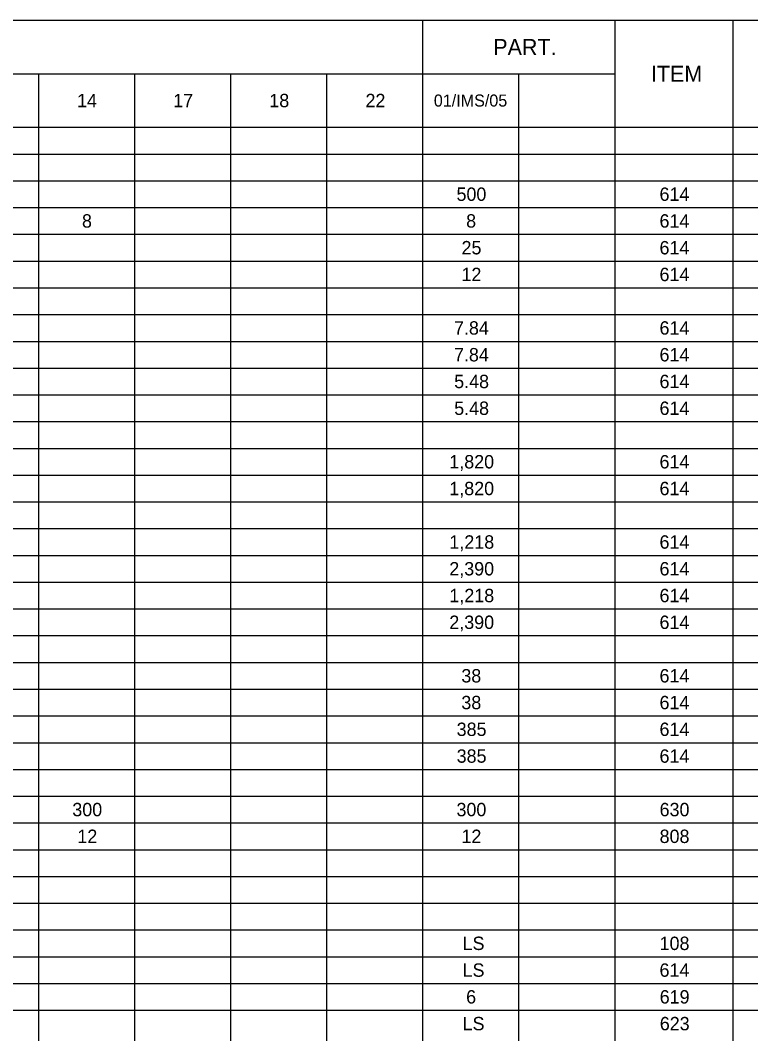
# Model space of a CAD drawing. Extents: x -32.2 to 34, y 0 to 22.
# Drawn here: x -24.34 to -16.7, y 10.89 to 21.5 of the extents above; entities that cross this region are included whole.
import ezdxf

# ---------------------------------------------------------------- set-up
doc = ezdxf.new("R2010")
doc.units = 0
doc.layers.add('SH_Text', color=7, linetype='Continuous')

msp = doc.modelspace()

# ---------------------------------------------------------------- linework, layer by layer
at = {"layer": 'SH_Text'}
for p, q in [((-32.188, 21.5), (-1.685, 21.5)), ((-20.132, 21.5), (-20.132, 0.5)), ((-18.122, 21.5), (-18.122, 0.5)), ((-16.887, 21.5), (-16.887, 0.5)), ((-32.188, 20.94), (-18.122, 20.94)), ((-24.151, 20.94), (-24.151, 0.5)), ((-23.146, 20.94), (-23.146, 0.5)), ((-22.141, 20.94), (-22.141, 0.5)), ((-21.137, 20.94), (-21.137, 0.5)), ((-19.127, 20.94), (-19.127, 0.5)), ((-32.188, 20.38), (-1.685, 20.38)), ((-32.188, 20.1), (-1.685, 20.1)), ((-32.188, 19.82), (-1.685, 19.82)), ((-32.188, 19.54), (-1.685, 19.54)), ((-32.188, 19.26), (-1.685, 19.26)), ((-32.188, 18.98), (-1.685, 18.98)), ((-32.188, 18.7), (-1.685, 18.7)), ((-32.188, 18.42), (-1.685, 18.42)), ((-32.188, 18.14), (-1.685, 18.14)), ((-32.188, 17.86), (-1.685, 17.86)), ((-32.188, 17.58), (-1.685, 17.58)), ((-32.188, 17.3), (-1.685, 17.3)), ((-32.188, 17.02), (-1.685, 17.02)), ((-32.188, 16.74), (-1.685, 16.74)), ((-32.188, 16.46), (-1.685, 16.46)), ((-32.188, 16.18), (-1.685, 16.18)), ((-32.188, 15.9), (-1.685, 15.9)), ((-32.188, 15.62), (-1.685, 15.62)), ((-32.188, 15.34), (-1.685, 15.34)), ((-32.188, 15.06), (-1.685, 15.06)), ((-32.188, 14.78), (-1.685, 14.78)), ((-32.188, 14.5), (-1.685, 14.5)), ((-32.188, 14.22), (-1.685, 14.22)), ((-32.188, 13.94), (-1.685, 13.94)), ((-32.188, 13.66), (-1.685, 13.66)), ((-32.188, 13.38), (-1.685, 13.38)), ((-32.188, 13.1), (-1.685, 13.1)), ((-32.188, 12.82), (-1.685, 12.82)), ((-32.188, 12.54), (-1.685, 12.54)), ((-32.188, 12.26), (-1.685, 12.26)), ((-32.188, 11.98), (-1.685, 11.98)), ((-32.188, 11.7), (-1.685, 11.7)), ((-32.188, 11.42), (-1.685, 11.42)), ((-32.188, 11.14), (-1.685, 11.14))]:
    msp.add_line(p, q, dxfattribs=at)

# ---------------------------------------------------------------- texts
for s, height, p in [('PART.', 0.168, (-19.392, 21.136)), ('ITEM', 0.168, (-17.743, 20.856)), ('14', 0.14, (-23.746, 20.59)), ('17', 0.14, (-22.74, 20.59)), ('18', 0.14, (-21.735, 20.59)), ('22', 0.14, (-20.729, 20.59)), ('01/IMS/05', 0.126, (-20.014, 20.597)), ('500', 0.14, (-19.777, 19.61)), ('614', 0.14, (-17.653, 19.61)), ('8', 0.14, (-23.695, 19.33)), ('8', 0.14, (-19.676, 19.33)), ('614', 0.14, (-17.653, 19.33)), ('25', 0.14, (-19.724, 19.05)), ('614', 0.14, (-17.653, 19.05)), ('12', 0.14, (-19.725, 18.77)), ('614', 0.14, (-17.653, 18.77)), ('7.84', 0.14, (-19.803, 18.21)), ('614', 0.14, (-17.653, 18.21)), ('7.84', 0.14, (-19.803, 17.93)), ('614', 0.14, (-17.653, 17.93)), ('5.48', 0.14, (-19.801, 17.65)), ('614', 0.14, (-17.653, 17.65)), ('5.48', 0.14, (-19.801, 17.37)), ('614', 0.14, (-17.653, 17.37)), ('1,820', 0.14, (-19.852, 16.81)), ('614', 0.14, (-17.653, 16.81)), ('1,820', 0.14, (-19.852, 16.53)), ('614', 0.14, (-17.653, 16.53)), ('1,218', 0.14, (-19.851, 15.97)), ('614', 0.14, (-17.653, 15.97)), ('2,390', 0.14, (-19.852, 15.69)), ('614', 0.14, (-17.653, 15.69)), ('1,218', 0.14, (-19.851, 15.41)), ('614', 0.14, (-17.653, 15.41)), ('2,390', 0.14, (-19.852, 15.13)), ('614', 0.14, (-17.653, 15.13)), ('38', 0.14, (-19.726, 14.57)), ('614', 0.14, (-17.653, 14.57)), ('38', 0.14, (-19.726, 14.29)), ('614', 0.14, (-17.653, 14.29)), ('385', 0.14, (-19.775, 14.01)), ('614', 0.14, (-17.653, 14.01)), ('385', 0.14, (-19.775, 13.73)), ('614', 0.14, (-17.653, 13.73)), ('300', 0.14, (-23.796, 13.17)), ('300', 0.14, (-19.777, 13.17)), ('630', 0.14, (-17.652, 13.17)), ('12', 0.14, (-23.743, 12.89)), ('12', 0.14, (-19.725, 12.89)), ('808', 0.14, (-17.652, 12.89)), ('LS', 0.14, (-19.713, 11.77)), ('108', 0.14, (-17.652, 11.77)), ('LS', 0.14, (-19.713, 11.49)), ('614', 0.14, (-17.653, 11.49)), ('6', 0.14, (-19.676, 11.21)), ('619', 0.14, (-17.651, 11.21)), ('LS', 0.14, (-19.713, 10.93)), ('623', 0.14, (-17.65, 10.93))]:
    msp.add_text(s, height=height, dxfattribs=at).set_placement(p)

doc.saveas('drawing.dxf')
